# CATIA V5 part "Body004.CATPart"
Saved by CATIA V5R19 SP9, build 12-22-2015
Part number: Body004
Definition: design
Nomenclature: Body004
Source: Unknown
Bounding box of the stored display mesh (mm): x -5 to 7.5, y -70.49 to -63.49, z 0 to 2
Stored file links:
  Z:\charly_robot\Body004.CATPart
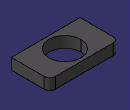
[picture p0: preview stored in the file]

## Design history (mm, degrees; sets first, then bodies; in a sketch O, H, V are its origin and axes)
AxisSystem1: origin (0, 0, 0), X (1, 0, 0), Y (0, 1, 0), Z (0, 0, 1)
Body1 "MANIFOLD_SOLID_BREP #35528" (main body)
  Solid1: solid without history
